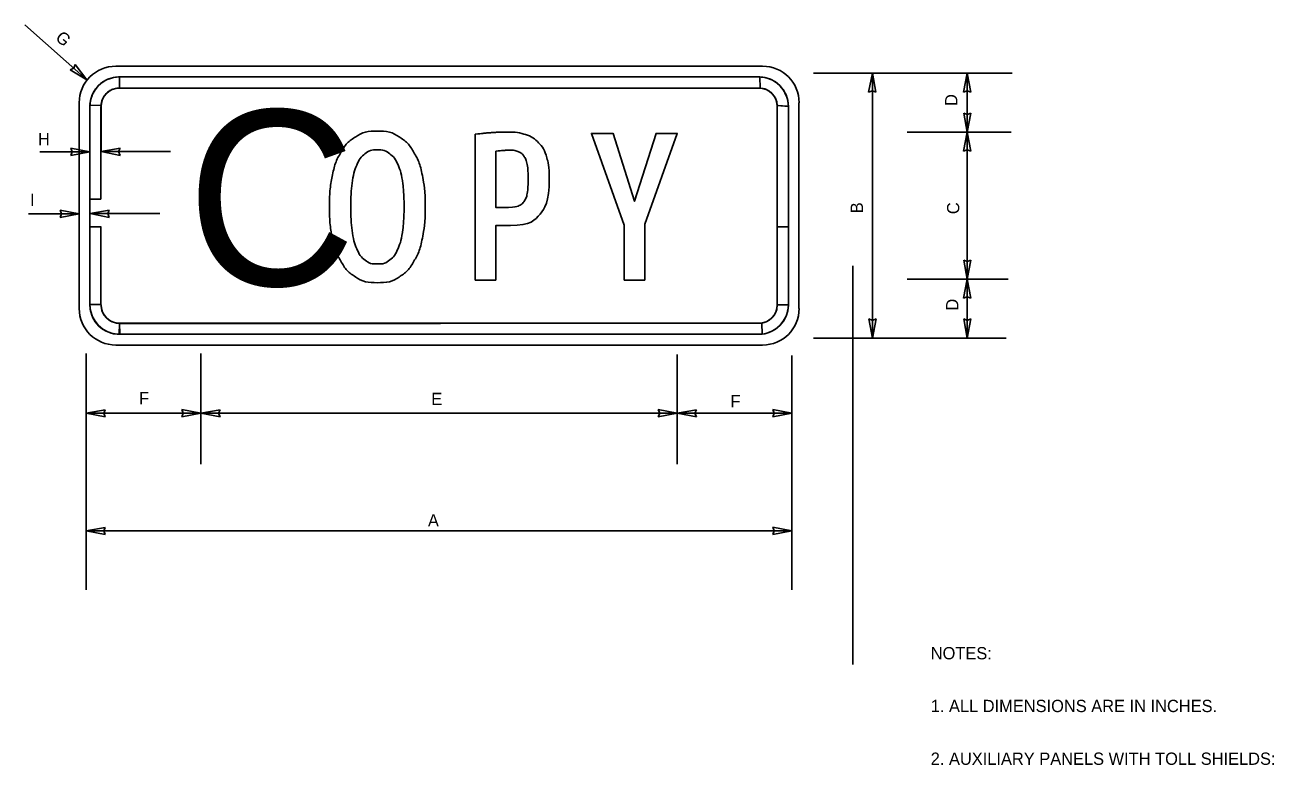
# Model space of a CAD drawing. Extents: x 60714 to 61340, y 8039 to 8429.
# Drawn here: x 60778.4 to 61063.3, y 8253.1 to 8421.9 of the extents above; entities that cross this region are included whole.
import ezdxf

# ---------------------------------------------------------------- set-up
doc = ezdxf.new("R2010")
doc.units = 0
for name, color, linetype in [('DimLines_dp', 7, 'Continuous'), ('SignPanel', 7, 'Continuous'), ('TextNotes', 7, 'Continuous')]:
    doc.layers.add(name, color=color, linetype=linetype)

msp = doc.modelspace()

# ---------------------------------------------------------------- linework, layer by layer
at = {"layer": 'DimLines_dp'}
for p, q in [((60792.49, 8409.32), (60778.36, 8421.85)), ((60789.48, 8411.98), (60788.7, 8411.6)), ((60789.48, 8411.98), (60788.7, 8411.6)), ((60788.7, 8411.6), (60792.49, 8409.32)), ((60788.7, 8411.6), (60792.49, 8409.32)), ((60789.79, 8412.83), (60789.48, 8411.98)), ((60789.79, 8412.83), (60789.48, 8411.98)), ((60792.49, 8409.32), (60789.79, 8412.83)), ((60792.49, 8409.32), (60789.79, 8412.83)), ((61003.58, 8410.85), (60958.21, 8410.85)), ((60971.66, 8410.85), (60970.82, 8406.5)), ((60971.66, 8410.85), (60970.82, 8406.5)), ((60971.66, 8410.85), (60971.66, 8350.45)), ((60972.47, 8406.5), (60971.66, 8410.85)), ((60972.47, 8406.5), (60971.66, 8410.85)), ((60993.32, 8410.85), (60992.48, 8406.5)), ((60993.32, 8410.85), (60992.48, 8406.5)), ((60993.32, 8397.4), (60993.32, 8410.85)), ((60994.13, 8406.5), (60993.32, 8410.85)), ((60994.13, 8406.5), (60993.32, 8410.85)), ((60970.82, 8406.5), (60971.66, 8406.83)), ((60970.82, 8406.5), (60971.66, 8406.83)), ((60971.66, 8406.83), (60972.47, 8406.5)), ((60971.66, 8406.83), (60972.47, 8406.5)), ((60992.48, 8406.5), (60993.32, 8406.83)), ((60992.48, 8406.5), (60993.32, 8406.83)), ((60993.32, 8406.83), (60994.13, 8406.5)), ((60993.32, 8406.83), (60994.13, 8406.5)), ((60993.32, 8401.42), (60992.51, 8401.75)), ((60992.51, 8401.75), (60993.32, 8397.4)), ((60993.32, 8401.42), (60992.51, 8401.75)), ((60992.51, 8401.75), (60993.32, 8397.4)), ((60993.32, 8397.4), (60994.16, 8401.75)), ((60994.16, 8401.75), (60993.32, 8401.42)), ((60993.32, 8397.4), (60994.16, 8401.75)), ((60994.16, 8401.75), (60993.32, 8401.42)), ((60979.59, 8397.4), (61003.34, 8397.4)), ((60993.32, 8397.4), (60992.48, 8393.05)), ((60993.32, 8397.4), (60992.48, 8393.05)), ((60993.32, 8397.4), (60993.32, 8363.86)), ((60994.13, 8393.05), (60993.32, 8397.4)), ((60994.13, 8393.05), (60993.32, 8397.4)), ((60793.18, 8392.92), (60781.71, 8392.92)), ((60793.18, 8392.92), (60788.83, 8393.76)), ((60788.83, 8393.76), (60789.16, 8392.92)), ((60793.18, 8392.92), (60788.83, 8393.76)), ((60788.83, 8393.76), (60789.16, 8392.92)), ((60789.16, 8392.92), (60788.83, 8392.11)), ((60788.83, 8392.11), (60793.18, 8392.92)), ((60789.16, 8392.92), (60788.83, 8392.11)), ((60788.83, 8392.11), (60793.18, 8392.92)), ((60800.05, 8393.77), (60795.7, 8392.97)), ((60800.05, 8393.77), (60795.7, 8392.97)), ((60795.7, 8392.97), (60811.57, 8392.97)), ((60795.7, 8392.97), (60800.05, 8392.12)), ((60795.7, 8392.97), (60800.05, 8392.12)), ((60799.72, 8392.97), (60800.05, 8393.77)), ((60799.72, 8392.97), (60800.05, 8393.77)), ((60800.05, 8392.12), (60799.72, 8392.97)), ((60800.05, 8392.12), (60799.72, 8392.97)), ((60992.48, 8393.05), (60993.32, 8393.38)), ((60992.48, 8393.05), (60993.32, 8393.38)), ((60993.32, 8393.38), (60994.13, 8393.05)), ((60993.32, 8393.38), (60994.13, 8393.05)), ((60790.72, 8378.75), (60779.16, 8378.75)), ((60790.72, 8378.75), (60786.37, 8379.59)), ((60786.37, 8379.59), (60786.7, 8378.75)), ((60790.72, 8378.75), (60786.37, 8379.59)), ((60786.37, 8379.59), (60786.7, 8378.75)), ((60786.7, 8378.75), (60786.37, 8377.94)), ((60786.37, 8377.94), (60790.72, 8378.75)), ((60786.7, 8378.75), (60786.37, 8377.94)), ((60786.37, 8377.94), (60790.72, 8378.75)), ((60797.6, 8379.63), (60793.25, 8378.82)), ((60797.6, 8379.63), (60793.25, 8378.82)), ((60793.25, 8378.82), (60809.11, 8378.82)), ((60793.25, 8378.82), (60797.6, 8377.98)), ((60793.25, 8378.82), (60797.6, 8377.98)), ((60797.27, 8378.82), (60797.6, 8379.63)), ((60797.27, 8378.82), (60797.6, 8379.63)), ((60797.6, 8377.98), (60797.27, 8378.82)), ((60797.6, 8377.98), (60797.27, 8378.82)), ((60967.21, 8276.01), (60967.21, 8366.92)), ((60993.32, 8367.88), (60992.51, 8368.21)), ((60992.51, 8368.21), (60993.32, 8363.86)), ((60993.32, 8367.88), (60992.51, 8368.21)), ((60992.51, 8368.21), (60993.32, 8363.86)), ((60993.32, 8363.86), (60994.16, 8368.21)), ((60994.16, 8368.21), (60993.32, 8367.88)), ((60993.32, 8363.86), (60994.16, 8368.21)), ((60994.16, 8368.21), (60993.32, 8367.88)), ((60979.59, 8363.86), (61002.66, 8363.86)), ((60993.32, 8363.86), (60992.48, 8359.51)), ((60993.32, 8363.86), (60992.48, 8359.51)), ((60993.32, 8363.86), (60993.32, 8350.45)), ((60994.13, 8359.51), (60993.32, 8363.86)), ((60994.13, 8359.51), (60993.32, 8363.86)), ((60992.48, 8359.51), (60993.32, 8359.84)), ((60992.48, 8359.51), (60993.32, 8359.84)), ((60993.32, 8359.84), (60994.13, 8359.51)), ((60993.32, 8359.84), (60994.13, 8359.51)), ((60971.66, 8354.47), (60970.85, 8354.8)), ((60970.85, 8354.8), (60971.66, 8350.45)), ((60971.66, 8354.47), (60970.85, 8354.8)), ((60970.85, 8354.8), (60971.66, 8350.45)), ((60971.66, 8350.45), (60972.5, 8354.8)), ((60972.5, 8354.8), (60971.66, 8354.47)), ((60971.66, 8350.45), (60972.5, 8354.8)), ((60972.5, 8354.8), (60971.66, 8354.47)), ((60993.32, 8354.47), (60992.51, 8354.8)), ((60992.51, 8354.8), (60993.32, 8350.45)), ((60993.32, 8350.45), (60994.16, 8354.8)), ((60994.16, 8354.8), (60993.32, 8354.47)), ((61002.22, 8350.45), (60958.21, 8350.45)), ((60792.33, 8346.91), (60792.33, 8293.04)), ((60818.5, 8346.91), (60818.5, 8321.67)), ((60927.17, 8346.67), (60927.17, 8321.67)), ((60953.3, 8346.47), (60953.3, 8293.04)), ((60796.68, 8334.11), (60792.33, 8333.3)), ((60796.68, 8334.11), (60792.33, 8333.3)), ((60792.33, 8333.3), (60818.5, 8333.3)), ((60792.33, 8333.3), (60796.68, 8332.46)), ((60792.33, 8333.3), (60796.68, 8332.46)), ((60796.35, 8333.3), (60796.68, 8334.11)), ((60796.35, 8333.3), (60796.68, 8334.11)), ((60796.68, 8332.46), (60796.35, 8333.3)), ((60796.68, 8332.46), (60796.35, 8333.3)), ((60818.5, 8333.3), (60814.15, 8334.14)), ((60814.15, 8334.14), (60814.48, 8333.3)), ((60818.5, 8333.3), (60814.15, 8334.14)), ((60814.15, 8334.14), (60814.48, 8333.3)), ((60814.48, 8333.3), (60814.15, 8332.49)), ((60814.15, 8332.49), (60818.5, 8333.3)), ((60814.48, 8333.3), (60814.15, 8332.49)), ((60814.15, 8332.49), (60818.5, 8333.3)), ((60822.85, 8334.11), (60818.5, 8333.3)), ((60822.85, 8334.11), (60818.5, 8333.3)), ((60818.5, 8333.3), (60927.17, 8333.3)), ((60818.5, 8333.3), (60822.85, 8332.46)), ((60818.5, 8333.3), (60822.85, 8332.46)), ((60822.52, 8333.3), (60822.85, 8334.11)), ((60822.52, 8333.3), (60822.85, 8334.11)), ((60822.85, 8332.46), (60822.52, 8333.3)), ((60822.85, 8332.46), (60822.52, 8333.3)), ((60927.17, 8333.3), (60922.82, 8334.14)), ((60922.82, 8334.14), (60923.15, 8333.3)), ((60923.15, 8333.3), (60922.82, 8332.49)), ((60922.82, 8332.49), (60927.17, 8333.3)), ((60931.52, 8334.11), (60927.17, 8333.3)), ((60931.52, 8334.11), (60927.17, 8333.3)), ((60927.17, 8333.3), (60953.3, 8333.3)), ((60927.17, 8333.3), (60931.52, 8332.46)), ((60927.17, 8333.3), (60931.52, 8332.46)), ((60931.19, 8333.3), (60931.52, 8334.11)), ((60931.19, 8333.3), (60931.52, 8334.11)), ((60931.52, 8332.46), (60931.19, 8333.3)), ((60931.52, 8332.46), (60931.19, 8333.3)), ((60953.3, 8333.3), (60948.95, 8334.14)), ((60948.95, 8334.14), (60949.28, 8333.3)), ((60953.3, 8333.3), (60948.95, 8334.14)), ((60948.95, 8334.14), (60949.28, 8333.3)), ((60949.28, 8333.3), (60948.95, 8332.49)), ((60948.95, 8332.49), (60953.3, 8333.3)), ((60949.28, 8333.3), (60948.95, 8332.49)), ((60948.95, 8332.49), (60953.3, 8333.3)), ((60796.68, 8307.26), (60792.33, 8306.45)), ((60796.68, 8307.26), (60792.33, 8306.45)), ((60792.33, 8306.45), (60953.3, 8306.45)), ((60792.33, 8306.45), (60796.68, 8305.61)), ((60792.33, 8306.45), (60796.68, 8305.61)), ((60796.35, 8306.45), (60796.68, 8307.26)), ((60796.35, 8306.45), (60796.68, 8307.26)), ((60796.68, 8305.61), (60796.35, 8306.45)), ((60796.68, 8305.61), (60796.35, 8306.45)), ((60953.3, 8306.45), (60948.95, 8307.29)), ((60948.95, 8307.29), (60949.28, 8306.45)), ((60953.3, 8306.45), (60948.95, 8307.29)), ((60948.95, 8307.29), (60949.28, 8306.45)), ((60949.28, 8306.45), (60948.95, 8305.64)), ((60948.95, 8305.64), (60953.3, 8306.45)), ((60949.28, 8306.45), (60948.95, 8305.64)), ((60948.95, 8305.64), (60953.3, 8306.45))]:
    msp.add_line(p, q, dxfattribs=at)
at = {"layer": 'SignPanel'}
for p, q in [((60799.06, 8412.46), (60946.62, 8412.46)), ((60799.9, 8410), (60945.77, 8410)), ((60799.9, 8407.47), (60945.77, 8407.47)), ((60790.72, 8404.12), (60790.72, 8357.18)), ((60793.18, 8403.28), (60793.18, 8382.09)), ((60795.67, 8403.28), (60795.67, 8382.09)), ((60949.96, 8403.49), (60949.96, 8382.08)), ((60952.5, 8403.28), (60952.5, 8358.02)), ((60954.91, 8404.12), (60954.91, 8357.18)), ((60793.18, 8382.09), (60793.18, 8358.02)), ((60949.96, 8382.08), (60949.96, 8358.02)), ((60795.67, 8375.84), (60795.67, 8358.02)), ((60799.9, 8353.84), (60945.77, 8353.84)), ((60799.06, 8348.84), (60946.62, 8348.84)), ((60799.9, 8351.3), (60945.77, 8351.3))]:
    msp.add_line(p, q, dxfattribs=at)
for points in [[(60793.22, 8403.52), (60795.72, 8403.6), (60795.72, 8403.88), (60795.8, 8404.16), (60795.88, 8404.57), (60795.96, 8404.81), (60796.12, 8405.09), (60796.24, 8405.33), (60796.4, 8405.61), (60796.56, 8405.85), (60796.72, 8406.02), (60796.88, 8406.22), (60797.08, 8406.42), (60797.28, 8406.58), (60797.53, 8406.74), (60797.73, 8406.9), (60797.97, 8407.02), (60798.13, 8407.1), (60798.37, 8407.22), (60798.73, 8407.3), (60798.97, 8407.38), (60799.3, 8407.42), (60799.58, 8407.47), (60799.94, 8407.47), (60799.9, 8410), (60799.66, 8410), (60799.18, 8409.96), (60798.97, 8409.92), (60798.53, 8409.84), (60798.33, 8409.8), (60798.09, 8409.76), (60797.89, 8409.68), (60797.61, 8409.6), (60797.36, 8409.48), (60797.12, 8409.4), (60796.8, 8409.24), (60796.44, 8409.03), (60796.12, 8408.83), (60795.88, 8408.67), (60795.59, 8408.47), (60795.31, 8408.19), (60795.07, 8407.95), (60794.83, 8407.7), (60794.63, 8407.47), (60794.47, 8407.26), (60794.31, 8406.98), (60794.14, 8406.78), (60794.02, 8406.54), (60793.9, 8406.3), (60793.78, 8406.06), (60793.58, 8405.57), (60793.46, 8405.25), (60793.38, 8404.93), (60793.3, 8404.53), (60793.22, 8404.16), (60793.18, 8403.8)], [(60946.06, 8407.47), (60946.01, 8410), (60799.9, 8410), (60799.94, 8407.47)], [(60950.04, 8403.48), (60952.38, 8403.32), (60952.5, 8403.32), (60952.46, 8403.84), (60952.38, 8404.57), (60952.22, 8405.21), (60952.01, 8405.73), (60951.81, 8406.18), (60951.61, 8406.58), (60951.29, 8407.14), (60950.89, 8407.63), (60950.65, 8407.91), (60950.28, 8408.27), (60950.12, 8408.39), (60949.8, 8408.67), (60949.36, 8408.95), (60948.91, 8409.24), (60948.51, 8409.4), (60947.87, 8409.68), (60947.43, 8409.8), (60947.06, 8409.88), (60946.7, 8409.92), (60946.3, 8409.96), (60946.01, 8410), (60946.1, 8407.47), (60946.78, 8407.34), (60947.1, 8407.26), (60947.51, 8407.1), (60947.75, 8406.98), (60948.03, 8406.82), (60948.31, 8406.62), (60948.55, 8406.46), (60948.83, 8406.18), (60948.99, 8405.98), (60949.15, 8405.77), (60949.36, 8405.45), (60949.56, 8405.13), (60949.64, 8404.93), (60949.72, 8404.69), (60949.84, 8404.32), (60949.88, 8404.08), (60949.96, 8403.72)], [(60949.96, 8403.49), (60952.5, 8403.28), (60952.5, 8375.85), (60949.96, 8375.85)], [(60949.96, 8358.02), (60952.5, 8358.02), (60952.5, 8375.85), (60949.96, 8375.85)], [(60793.18, 8358.1), (60795.67, 8358.1), (60795.88, 8356.77), (60796.16, 8356.05), (60796.92, 8355.04), (60797.77, 8354.4), (60798.53, 8354.04), (60799.22, 8353.88), (60799.54, 8353.84), (60799.9, 8353.84), (60799.98, 8351.3), (60799.42, 8351.3), (60798.05, 8351.54), (60796.88, 8352.02), (60796.04, 8352.51), (60795.19, 8353.19), (60794.39, 8354.16), (60793.82, 8355.09), (60793.58, 8355.73), (60793.26, 8357.02)], [(60946.46, 8353.88), (60946.54, 8351.34), (60947.34, 8351.5), (60948.07, 8351.7), (60949.04, 8352.14), (60949.88, 8352.71), (60950.65, 8353.39), (60951.01, 8353.84), (60951.37, 8354.28), (60951.69, 8354.84), (60951.97, 8355.44), (60952.14, 8355.89), (60952.34, 8356.61), (60952.46, 8357.26), (60952.5, 8357.9), (60952.5, 8358.02), (60949.96, 8358.02), (60949.84, 8356.94), (60949.64, 8356.33), (60949.24, 8355.65), (60948.99, 8355.28), (60948.67, 8354.96), (60948.59, 8354.88), (60948.07, 8354.52), (60947.58, 8354.24), (60947.18, 8354.04)], [(60799.9, 8353.71), (60799.86, 8351.3), (60946.54, 8351.34), (60946.46, 8353.88)]]:
    msp.add_lwpolyline(points, close=True, dxfattribs=at)
for points in [[(60793.18, 8382.09), (60793.18, 8403.52), (60795.72, 8403.6), (60795.69, 8382.09)], [(60919.76, 8376.4), (60919.76, 8363.66), (60915.08, 8363.66), (60915.08, 8376.17), (60907.57, 8397.11), (60912.52, 8397.11), (60917.42, 8381.66), (60922.33, 8397.11), (60927.14, 8397.11), (60919.76, 8376.4)], [(60889.08, 8376.1), (60885.75, 8376.1), (60885.75, 8363.66), (60881.07, 8363.66), (60881.07, 8396.93)], [(60885.75, 8393.06), (60885.75, 8380.24), (60888.67, 8380.24)], [(60795.67, 8382.09), (60793.18, 8382.09)], [(60795.69, 8382.09), (60795.67, 8382.09)], [(60795.69, 8375.86), (60795.67, 8358.18), (60793.18, 8358.1), (60793.18, 8375.84)], [(60793.18, 8375.84), (60795.67, 8375.84), (60795.67, 8375.86)], [(60795.67, 8375.86), (60795.69, 8375.86)]]:
    msp.add_lwpolyline(points, dxfattribs=at)
for centre, radius, start, end in [((60799.06, 8404.13), 8.32, 90, 180), ((60946.63, 8404.13), 8.32, 0, 90), ((60799.9, 8403.29), 6.71, 90, 180), ((60945.79, 8403.29), 6.71, 0, 90), ((60799.9, 8403.29), 4.19, 90, 180), ((60945.79, 8403.29), 4.19, 0, 90), ((60799.06, 8357.18), 8.32, 180, 270), ((60799.9, 8358.02), 6.71, 180, 270), ((60799.9, 8358.02), 4.19, 180, 270), ((60945.79, 8358.02), 6.71, 270, 0), ((60945.79, 8358.02), 4.19, 270, 0), ((60946.63, 8357.18), 8.32, 270, 0)]:
    msp.add_arc(centre, radius, start, end, dxfattribs=at)
for points in [[(60869.68, 8380.41), (60869.68, 8376.63), (60869.05, 8373.45), (60868.42, 8370.27), (60867.08, 8367.97), (60865.75, 8365.66), (60863.69, 8364.37), (60861.63, 8363.08), (60858.77, 8363.08), (60855.87, 8363.08), (60853.81, 8364.37), (60851.75, 8365.66), (60850.42, 8367.97), (60849.08, 8370.27), (60848.45, 8373.45), (60847.82, 8376.63), (60847.82, 8380.41), (60847.82, 8384.15), (60848.45, 8387.31), (60849.08, 8390.47), (60850.4, 8392.76), (60851.72, 8395.05), (60853.8, 8396.34), (60855.87, 8397.63), (60858.77, 8397.63), (60861.63, 8397.63), (60863.69, 8396.34), (60865.75, 8395.05), (60867.08, 8392.76), (60868.42, 8390.47), (60869.05, 8387.31), (60869.68, 8384.15), (60869.68, 8380.41)], [(60881.07, 8396.93), (60882, 8397.03), (60882.84, 8397.13), (60883.69, 8397.23), (60884.57, 8397.29), (60885.44, 8397.36), (60886.4, 8397.39), (60887.35, 8397.43), (60888.49, 8397.43), (60890.8, 8397.43), (60892.57, 8396.84), (60894.34, 8396.26), (60895.54, 8394.99), (60896.74, 8393.72), (60897.35, 8391.69), (60897.97, 8389.67), (60897.97, 8386.76)], [(60864.84, 8380.42), (60864.84, 8383.43), (60864.52, 8385.84), (60864.2, 8388.25), (60863.46, 8389.93), (60862.73, 8391.6), (60861.56, 8392.49), (60860.39, 8393.37), (60858.7, 8393.37), (60857.07, 8393.37), (60855.92, 8392.47), (60854.77, 8391.57), (60854.05, 8389.88), (60853.33, 8388.19), (60853, 8385.79), (60852.68, 8383.4), (60852.68, 8380.42), (60852.68, 8377.38), (60853, 8374.95), (60853.33, 8372.52), (60854.05, 8370.83), (60854.77, 8369.14), (60855.94, 8368.24), (60857.1, 8367.34), (60858.79, 8367.34), (60860.45, 8367.34), (60861.6, 8368.26), (60862.76, 8369.18), (60863.48, 8370.88), (60864.2, 8372.59), (60864.52, 8375.02), (60864.84, 8377.44), (60864.84, 8380.42)], [(60893.16, 8386.76), (60893.16, 8388.54), (60892.96, 8389.78), (60892.76, 8391.01), (60892.27, 8391.8), (60891.77, 8392.59), (60890.96, 8392.94), (60890.15, 8393.29), (60888.95, 8393.29), (60888.18, 8393.29), (60887.41, 8393.22), (60886.64, 8393.16), (60885.75, 8393.06)], [(60888.67, 8380.24), (60890.05, 8380.24), (60890.91, 8380.59), (60891.77, 8380.94), (60892.28, 8381.71), (60892.79, 8382.48), (60892.97, 8383.72), (60893.16, 8384.96), (60893.16, 8386.76)], [(60897.97, 8386.76), (60897.97, 8381.32), (60895.85, 8378.71), (60893.72, 8376.1), (60889.08, 8376.1)]]:
    msp.add_open_spline(points, degree=3, dxfattribs=at)

# ---------------------------------------------------------------- texts
at = {"layer": 'DimLines_dp'}
for s, rotation, p in [('G', 318.4185, (60785.1, 8418.66)), ('D', 90, (60991.05, 8403.38)), ('B', 90, (60969.52, 8378.92)), ('C', 90, (60991.5, 8378.7)), ('D', 90, (60991.28, 8356.7))]:
    msp.add_text(s, height=2.8, rotation=rotation, dxfattribs=at).set_placement(p)
for s, p in [('H', (60781.32, 8394.44)), ('I', (60779.5, 8380.59)), ('F', (60804.37, 8335.35)), ('E', (60871.04, 8335.16)), ('F', (60939.3, 8334.68)), ('A', (60870.28, 8307.47))]:
    msp.add_text(s, height=2.8, dxfattribs=at).set_placement(p)
at = {"layer": 'SignPanel'}
msp.add_text('C', height=40, dxfattribs=at).set_placement((60815.24, 8362.42))
at = {"layer": 'TextNotes'}
for s, p in [('NOTES:', (60984.98, 8277.17)), ('1. ALL DIMENSIONS ARE IN INCHES.', (60984.98, 8265.14)), ('2. AUXILIARY PANELS WITH TOLL SHIELDS:', (60984.98, 8253.11))]:
    msp.add_text(s, height=2.8, dxfattribs=at).set_placement(p)

doc.saveas('drawing.dxf')
